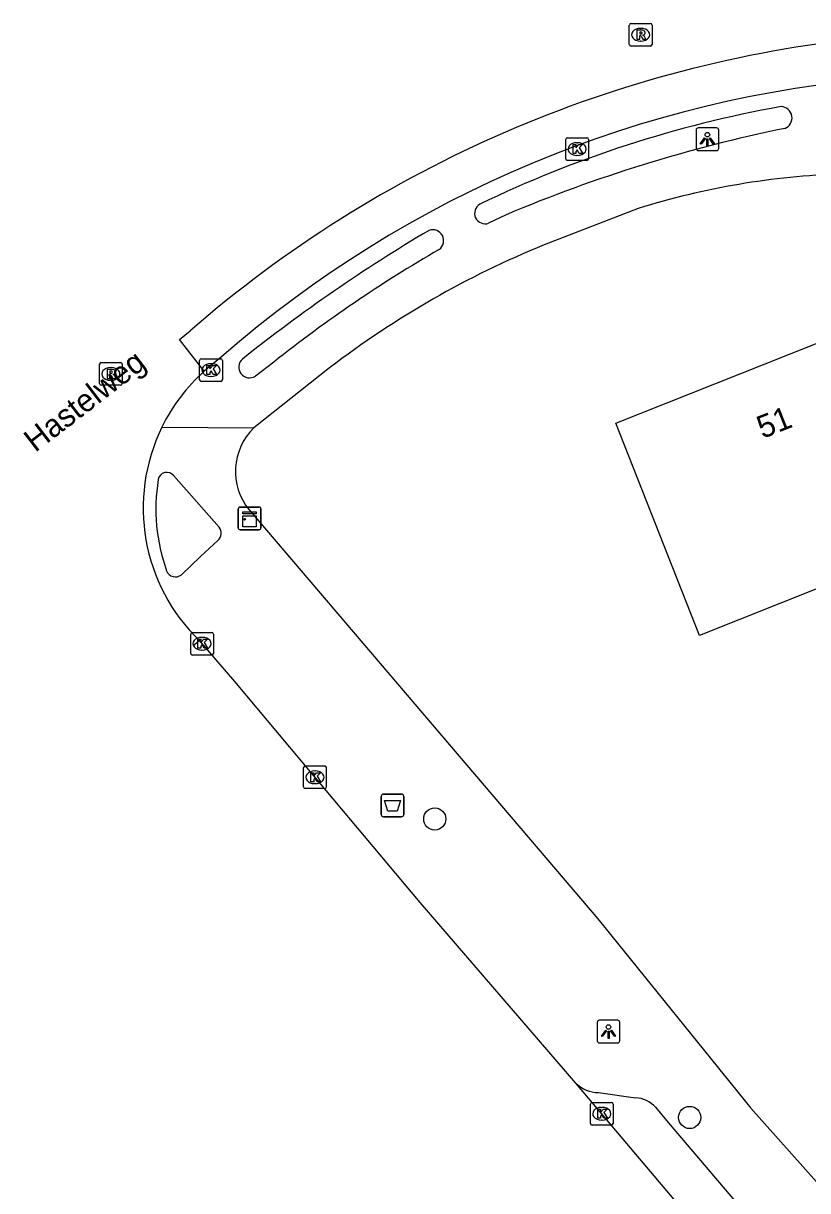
# Model space of a CAD drawing. Extents: x 159961 to 160856, y 382704 to 383353.
# Drawn here: x 159960.7 to 159995.3, y 383238.8 to 383290.2 of the extents above; entities that cross this region are included whole.
import ezdxf

# ---------------------------------------------------------------- set-up
doc = ezdxf.new("R2010")
doc.units = 0
for name, color, linetype in [('IMGEO_Afvalbak', 7, 'Continuous'), ('IMGEO_Boom', 7, 'Continuous'), ('IMGEO_Kast', 7, 'Continuous'), ('IMGEO_Kolk', 7, 'Continuous'), ('IMGEO_Lichtpunt', 7, 'Continuous'), ('IMGEO_Openbare_ruimte_label', 7, 'Continuous'), ('IMGEO_Pand', 7, 'Continuous'), ('IMGEO_Pand_nummerreeks', 7, 'Continuous'), ('IMGEO_Rijbaan_lokaal_gesloten', 7, 'Continuous'), ('IMGEO_Rijbaan_lokaal_open', 7, 'Continuous'), ('IMGEO_Rioolput', 7, 'Continuous'), ('IMGEO_Voetpad_open', 7, 'Continuous')]:
    doc.layers.add(name, color=color, linetype=linetype)

msp = doc.modelspace()

# ---------------------------------------------------------------- linework, layer by layer
at = {"layer": 'IMGEO_Afvalbak'}
for p, q in [((159976.475, 383255.351), (159976.475, 383256.151)), ((159976.475, 383256.151), (159976.475, 383255.351)), ((159976.575, 383256.251), (159977.365, 383256.251)), ((159977.365, 383256.251), (159976.575, 383256.251)), ((159977.465, 383256.151), (159977.465, 383255.351)), ((159977.465, 383255.351), (159977.465, 383256.151)), ((159977.365, 383255.251), (159976.575, 383255.251)), ((159976.575, 383255.251), (159977.365, 383255.251))]:
    msp.add_line(p, q, dxfattribs=at)
msp.add_lwpolyline([(159976.618, 383255.965), (159977.322, 383255.965), (159977.173, 383255.495), (159976.767, 383255.495), (159976.618, 383255.965)], dxfattribs=at)
for centre, start, end in [((159976.575, 383256.151), 90, 180), ((159976.575, 383256.151), 90, 180), ((159977.365, 383256.151), 0, 90), ((159977.365, 383256.151), 360, 90), ((159976.575, 383255.351), 180, 270), ((159976.575, 383255.351), 180, 270), ((159977.365, 383255.351), 270, 0), ((159977.365, 383255.351), 270, 0)]:
    msp.add_arc(centre, 0.1, start, end, dxfattribs=at)
at = {"layer": 'IMGEO_Boom'}
for centre in [(159978.834, 383255.154), (159990.063, 383242.015)]:
    msp.add_circle(centre, 0.489, dxfattribs=at)
at = {"layer": 'IMGEO_Kast'}
for p, q in [((159970.254, 383268.887), (159971.095, 383268.887)), ((159971.095, 383268.887), (159970.254, 383268.887)), ((159971.179, 383268.812), (159971.179, 383267.971)), ((159971.179, 383267.971), (159971.179, 383268.812)), ((159970.179, 383267.962), (159970.179, 383268.803)), ((159970.179, 383268.803), (159970.179, 383267.962)), ((159971.104, 383267.887), (159970.263, 383267.887)), ((159970.263, 383267.887), (159971.104, 383267.887))]:
    msp.add_line(p, q, dxfattribs=at)
for points in [[(159970.374, 383268.677), (159970.974, 383268.677), (159970.974, 383268.592), (159970.374, 383268.592), (159970.374, 383268.677)], [(159970.374, 383268.502), (159970.974, 383268.502), (159970.974, 383268.013), (159970.374, 383268.013), (159970.374, 383268.502)]]:
    msp.add_lwpolyline(points, dxfattribs=at)
msp.add_circle((159970.458, 383268.351), 0.0377, dxfattribs=at)
for centre, start, end in [((159970.257, 383268.809), 92.4484, 184.2845), ((159970.257, 383268.809), 92.4484, 184.2845), ((159971.101, 383268.809), 2.4484, 94.2845), ((159971.101, 383268.809), 2.4484, 94.2845), ((159970.257, 383267.965), 182.4484, 274.2845), ((159970.257, 383267.965), 182.4484, 274.2845), ((159971.101, 383267.965), 272.4484, 4.2845), ((159971.101, 383267.965), 272.4484, 4.2845)]:
    msp.add_arc(centre, 0.0779, start, end, dxfattribs=at)
at = {"layer": 'IMGEO_Kolk'}
for p, q in [((159984.603, 383284.217), (159984.603, 383285.069)), ((159984.678, 383285.143), (159985.53, 383285.143)), ((159985.091, 383284.923), (159985.116, 383284.923)), ((159985.604, 383285.069), (159985.604, 383284.217)), ((159985.114, 383284.363), (159985.089, 383284.363)), ((159985.53, 383284.143), (159984.678, 383284.143)), ((159968.478, 383274.491), (159968.478, 383275.343)), ((159968.553, 383275.417), (159969.405, 383275.417)), ((159968.966, 383275.197), (159968.991, 383275.197)), ((159969.479, 383275.343), (159969.479, 383274.491)), ((159968.989, 383274.637), (159968.964, 383274.637)), ((159969.405, 383274.417), (159968.553, 383274.417)), ((159968.084, 383262.444), (159968.084, 383263.296)), ((159968.159, 383263.37), (159969.011, 383263.37)), ((159969.085, 383263.296), (159969.085, 383262.444)), ((159968.572, 383263.15), (159968.597, 383263.15)), ((159969.011, 383262.37), (159968.159, 383262.37)), ((159968.595, 383262.59), (159968.57, 383262.59)), ((159973.056, 383256.565), (159973.056, 383257.417)), ((159973.131, 383257.491), (159973.983, 383257.491)), ((159973.544, 383257.271), (159973.569, 383257.271)), ((159974.057, 383257.417), (159974.057, 383256.565)), ((159973.983, 383256.491), (159973.131, 383256.491)), ((159973.567, 383256.711), (159973.542, 383256.711)), ((159985.689, 383241.751), (159985.689, 383242.603)), ((159985.764, 383242.677), (159986.616, 383242.677)), ((159986.69, 383242.603), (159986.69, 383241.751)), ((159986.177, 383242.457), (159986.202, 383242.457)), ((159986.616, 383241.677), (159985.764, 383241.677)), ((159986.2, 383241.897), (159986.175, 383241.897))]:
    msp.add_line(p, q, dxfattribs=at)
for points in [[(159984.603, 383284.217), (159984.603, 383285.069)], [(159984.678, 383285.143), (159985.53, 383285.143)], [(159984.924, 383284.843), (159985.047, 383284.843), (159985.047, 383284.692), (159985.177, 383284.843), (159985.341, 383284.843), (159985.195, 383284.692), (159985.348, 383284.443), (159985.196, 383284.443), (159985.111, 383284.607), (159985.047, 383284.54), (159985.047, 383284.443), (159984.924, 383284.443), (159984.924, 383284.843)], [(159985.604, 383285.069), (159985.604, 383284.217)], [(159985.53, 383284.143), (159984.678, 383284.143)], [(159968.478, 383274.491), (159968.478, 383275.343)], [(159968.553, 383275.417), (159969.405, 383275.417)], [(159968.799, 383275.117), (159968.922, 383275.117), (159968.922, 383274.966), (159969.052, 383275.117), (159969.216, 383275.117), (159969.07, 383274.966), (159969.223, 383274.717), (159969.071, 383274.717), (159968.986, 383274.881), (159968.922, 383274.814), (159968.922, 383274.717), (159968.799, 383274.717), (159968.799, 383275.117)], [(159969.479, 383275.343), (159969.479, 383274.491)], [(159969.405, 383274.417), (159968.553, 383274.417)], [(159968.084, 383262.444), (159968.084, 383263.296)], [(159968.159, 383263.37), (159969.011, 383263.37)], [(159969.085, 383263.296), (159969.085, 383262.444)], [(159968.405, 383263.07), (159968.528, 383263.07), (159968.528, 383262.919), (159968.658, 383263.07), (159968.822, 383263.07), (159968.676, 383262.919), (159968.829, 383262.67), (159968.677, 383262.67), (159968.592, 383262.834), (159968.528, 383262.767), (159968.528, 383262.67), (159968.405, 383262.67), (159968.405, 383263.07)], [(159969.011, 383262.37), (159968.159, 383262.37)], [(159973.056, 383256.565), (159973.056, 383257.417)], [(159973.131, 383257.491), (159973.983, 383257.491)], [(159973.377, 383257.191), (159973.5, 383257.191), (159973.5, 383257.04), (159973.63, 383257.191), (159973.794, 383257.191), (159973.648, 383257.04), (159973.801, 383256.791), (159973.649, 383256.791), (159973.564, 383256.955), (159973.5, 383256.888), (159973.5, 383256.791), (159973.377, 383256.791), (159973.377, 383257.191)], [(159974.057, 383257.417), (159974.057, 383256.565)], [(159973.983, 383256.491), (159973.131, 383256.491)], [(159985.689, 383241.751), (159985.689, 383242.603)], [(159985.764, 383242.677), (159986.616, 383242.677)], [(159986.69, 383242.603), (159986.69, 383241.751)], [(159986.01, 383242.377), (159986.133, 383242.377), (159986.133, 383242.226), (159986.263, 383242.377), (159986.427, 383242.377), (159986.281, 383242.226), (159986.434, 383241.977), (159986.282, 383241.977), (159986.197, 383242.141), (159986.133, 383242.074), (159986.133, 383241.977), (159986.01, 383241.977), (159986.01, 383242.377)], [(159986.616, 383241.677), (159985.764, 383241.677)]]:
    msp.add_lwpolyline(points, dxfattribs=at)
for centre, start, end in [((159984.68, 383285.067), 91.552, 178.448), ((159984.68, 383285.067), 91.552, 178.448), ((159985.528, 383285.067), 1.552, 88.448), ((159985.528, 383285.067), 1.552, 88.448), ((159984.68, 383284.219), 181.552, 268.448), ((159984.68, 383284.219), 181.552, 268.448), ((159985.528, 383284.219), 271.552, 358.448), ((159985.528, 383284.219), 271.552, 358.448), ((159968.555, 383275.341), 91.552, 178.448), ((159968.555, 383275.341), 91.552, 178.448), ((159969.403, 383275.341), 1.552, 88.448), ((159969.403, 383275.341), 1.552, 88.448), ((159968.555, 383274.493), 181.552, 268.448), ((159968.555, 383274.493), 181.552, 268.448), ((159969.403, 383274.493), 271.552, 358.448), ((159969.403, 383274.493), 271.552, 358.448), ((159968.161, 383263.294), 91.552, 178.448), ((159968.161, 383263.294), 91.552, 178.448), ((159969.009, 383263.294), 1.552, 88.448), ((159969.009, 383263.294), 1.552, 88.448), ((159968.161, 383262.446), 181.552, 268.448), ((159968.161, 383262.446), 181.552, 268.448), ((159969.009, 383262.446), 271.552, 358.448), ((159969.009, 383262.446), 271.552, 358.448), ((159973.133, 383257.415), 91.552, 178.448), ((159973.133, 383257.415), 91.552, 178.448), ((159973.981, 383257.415), 1.552, 88.448), ((159973.981, 383257.415), 1.552, 88.448), ((159973.133, 383256.567), 181.552, 268.448), ((159973.133, 383256.567), 181.552, 268.448), ((159973.981, 383256.567), 271.552, 358.448), ((159973.981, 383256.567), 271.552, 358.448), ((159985.766, 383242.601), 91.552, 178.448), ((159985.766, 383242.601), 91.552, 178.448), ((159986.614, 383242.601), 1.552, 88.448), ((159986.614, 383242.601), 1.552, 88.448), ((159985.766, 383241.753), 181.552, 268.448), ((159985.766, 383241.753), 181.552, 268.448), ((159986.614, 383241.753), 271.552, 358.448), ((159986.614, 383241.753), 271.552, 358.448)]:
    msp.add_arc(centre, 0.0765, start, end, dxfattribs=at)
for centre, major_axis, ratio, start_param, end_param in [((159985.09, 383284.643), (-0.387, 0.002), 0.722429, 4.712389, 7.853982), ((159985.115, 383284.643), (-0.39, 0.002), 0.717154, 1.570796, 4.712389), ((159968.965, 383274.917), (-0.387, 0.002), 0.722429, 4.712389, 7.853982), ((159968.99, 383274.917), (-0.39, 0.002), 0.717154, 1.570796, 4.712389), ((159968.571, 383262.87), (-0.387, 0.002), 0.722429, 4.712389, 7.853982), ((159968.596, 383262.87), (-0.39, 0.002), 0.717154, 1.570796, 4.712389), ((159973.543, 383256.991), (-0.387, 0.002), 0.722429, 4.712389, 7.853982), ((159973.568, 383256.991), (-0.39, 0.002), 0.717154, 1.570796, 4.712389), ((159986.176, 383242.177), (-0.387, 0.002), 0.722429, 4.712389, 7.853982), ((159986.201, 383242.177), (-0.39, 0.002), 0.717154, 1.570796, 4.712389)]:
    msp.add_ellipse(centre, major_axis=major_axis, ratio=ratio, start_param=start_param, end_param=end_param, dxfattribs=at)
at = {"layer": 'IMGEO_Lichtpunt'}
for p, q in [((159990.342, 383285.48), (159990.342, 383284.673)), ((159990.342, 383285.48), (159990.342, 383284.673)), ((159991.244, 383285.575), (159990.436, 383285.575)), ((159991.244, 383285.575), (159990.436, 383285.575)), ((159991.338, 383284.673), (159991.338, 383285.48)), ((159991.338, 383284.673), (159991.338, 383285.48)), ((159990.436, 383284.579), (159991.244, 383284.579)), ((159990.436, 383284.579), (159991.244, 383284.579)), ((159985.987, 383246.199), (159985.987, 383245.392)), ((159985.987, 383246.199), (159985.987, 383245.392)), ((159986.889, 383246.294), (159986.081, 383246.294)), ((159986.889, 383246.294), (159986.081, 383246.294)), ((159986.983, 383245.392), (159986.983, 383246.199)), ((159986.983, 383245.392), (159986.983, 383246.199)), ((159986.081, 383245.298), (159986.889, 383245.298)), ((159986.081, 383245.298), (159986.889, 383245.298))]:
    msp.add_line(p, q, dxfattribs=at)
for points in [[(159990.716, 383285.144), (159990.755, 383285.116), (159990.567, 383284.854), (159990.529, 383284.881), (159990.716, 383285.144)], [(159990.818, 383285.096), (159990.865, 383285.096), (159990.865, 383284.774), (159990.818, 383284.774), (159990.818, 383285.096)], [(159990.928, 383285.116), (159990.966, 383285.143), (159991.153, 383284.881), (159991.114, 383284.853), (159990.928, 383285.116)], [(159986.361, 383245.863), (159986.4, 383245.835), (159986.212, 383245.573), (159986.174, 383245.6), (159986.361, 383245.863)], [(159986.463, 383245.815), (159986.51, 383245.815), (159986.51, 383245.493), (159986.463, 383245.493), (159986.463, 383245.815)], [(159986.573, 383245.835), (159986.611, 383245.862), (159986.798, 383245.6), (159986.759, 383245.572), (159986.573, 383245.835)]]:
    msp.add_lwpolyline(points, dxfattribs=at)
for centre in [(159990.841, 383285.278), (159986.486, 383245.997)]:
    msp.add_circle(centre, 0.0994, dxfattribs=at)
for centre, start, end in [((159990.436, 383285.48), 90, 180), ((159990.436, 383285.48), 90, 180), ((159991.244, 383285.48), 0, 90), ((159991.244, 383285.48), 0, 90), ((159990.436, 383284.673), 180, 270), ((159990.436, 383284.673), 180, 270), ((159991.244, 383284.673), 270, 0), ((159991.244, 383284.673), 270, 360), ((159986.081, 383246.199), 90, 180), ((159986.081, 383246.199), 90, 180), ((159986.889, 383246.199), 0, 90), ((159986.889, 383246.199), 0, 90), ((159986.081, 383245.392), 180, 270), ((159986.081, 383245.392), 180, 270), ((159986.889, 383245.392), 270, 0), ((159986.889, 383245.392), 270, 360)]:
    msp.add_arc(centre, 0.0946, start, end, dxfattribs=at)
at = {"layer": 'IMGEO_Pand'}
msp.add_lwpolyline([(160002.018, 383262.712), (160000.276, 383267.111), (159998.559, 383266.431), (159999.041, 383265.213), (159996.252, 383264.107), (159995.769, 383265.324), (159990.498, 383263.234), (159986.81, 383272.583), (159998.885, 383277.371), (160002.407, 383268.436), (160010.962, 383271.828), (160013.55, 383265.303), (160005.184, 383261.986), (160002.018, 383262.712)], dxfattribs=at)
at = {"layer": 'IMGEO_Rijbaan_lokaal_gesloten'}
msp.add_lwpolyline([(159969.46, 383275.517), (159968.683, 383274.873)], dxfattribs=at)
msp.add_arc((160002.595, 383237.495), 50.435, 94.3795, 131.0712, dxfattribs=at)
at = {"layer": 'IMGEO_Rijbaan_lokaal_open'}
for points in [[(159968.683, 383274.873), (159967.594, 383276.266), (159968.06, 383276.648)], [(159968.468, 383263.009), (159968.231, 383262.808)], [(159985.049, 383243.527), (159978.189, 383251.472), (159972.977, 383257.683), (159970.034, 383261.211), (159968.468, 383263.009)], [(159995.149, 383231.573), (159985.049, 383243.527)]]:
    msp.add_lwpolyline(points, dxfattribs=at)
for centre, radius, start, end in [((160003.271, 383236.118), 53.689, 95.8341, 130.983), ((159974.098, 383268.836), 8.109, 131.8929, 153.9085), ((159974.09, 383268.841), 8.1, 153.9113, 226.0483)]:
    msp.add_arc(centre, radius, start, end, dxfattribs=at)
at = {"layer": 'IMGEO_Rioolput'}
for p, q in [((159987.402, 383289.253), (159987.402, 383290.105)), ((159987.477, 383290.179), (159988.329, 383290.179)), ((159987.89, 383289.959), (159987.915, 383289.959)), ((159988.403, 383290.105), (159988.403, 383289.253)), ((159987.913, 383289.399), (159987.888, 383289.399)), ((159988.329, 383289.179), (159987.477, 383289.179)), ((159964.068, 383274.319), (159964.068, 383275.171)), ((159964.143, 383275.245), (159964.995, 383275.245)), ((159964.556, 383275.025), (159964.581, 383275.025)), ((159965.069, 383275.171), (159965.069, 383274.319)), ((159964.579, 383274.465), (159964.554, 383274.465)), ((159964.995, 383274.245), (159964.143, 383274.245))]:
    msp.add_line(p, q, dxfattribs=at)
for points in [[(159987.402, 383289.253), (159987.402, 383290.105)], [(159987.477, 383290.179), (159988.329, 383290.179)], [(159987.991, 383289.877), (159987.739, 383289.879), (159987.739, 383289.479)], [(159988.403, 383290.105), (159988.403, 383289.253)], [(159987.739, 383289.479), (159987.863, 383289.479), (159987.863, 383289.641), (159987.874, 383289.641)], [(159987.917, 383289.798), (159987.863, 383289.798), (159987.863, 383289.717)], [(159987.863, 383289.717), (159987.915, 383289.717)], [(159987.921, 383289.612), (159987.992, 383289.479), (159988.132, 383289.479), (159988.067, 383289.605)], [(159988.329, 383289.179), (159987.477, 383289.179)], [(159964.068, 383274.319), (159964.068, 383275.171)], [(159964.143, 383275.245), (159964.995, 383275.245)], [(159965.069, 383275.171), (159965.069, 383274.319)], [(159964.657, 383274.943), (159964.405, 383274.945), (159964.405, 383274.545)], [(159964.405, 383274.545), (159964.529, 383274.545), (159964.529, 383274.707), (159964.54, 383274.707)], [(159964.583, 383274.864), (159964.529, 383274.864), (159964.529, 383274.783)], [(159964.529, 383274.783), (159964.581, 383274.783)], [(159964.587, 383274.678), (159964.658, 383274.545), (159964.798, 383274.545), (159964.733, 383274.671)], [(159964.995, 383274.245), (159964.143, 383274.245)]]:
    msp.add_lwpolyline(points, dxfattribs=at)
for centre, radius, start, end in [((159987.479, 383290.103), 0.0765, 91.552, 178.448), ((159987.479, 383290.103), 0.0765, 91.552, 178.448), ((159987.99, 383289.767), 0.109, 350.3612, 89.416), ((159988.327, 383290.103), 0.0765, 1.552, 88.448), ((159988.327, 383290.103), 0.0765, 1.552, 88.448), ((159987.873, 383289.588), 0.0533, 26.0293, 88.6989), ((159987.899, 383289.906), 0.19, 274.7715, 282.9687), ((159987.923, 383289.702), 0.0964, 77.0061, 93.1865), ((159987.937, 383289.759), 0.0378, 276.6634, 79.6772), ((159987.988, 383289.767), 0.112, 277.5842, 350.9817), ((159987.972, 383289.552), 0.108, 29.5134, 73.7905), ((159987.479, 383289.255), 0.0765, 181.552, 268.448), ((159987.479, 383289.255), 0.0765, 181.552, 268.448), ((159988.327, 383289.255), 0.0765, 271.552, 358.448), ((159988.327, 383289.255), 0.0765, 271.552, 358.448), ((159964.145, 383275.169), 0.0765, 91.552, 178.448), ((159964.145, 383275.169), 0.0765, 91.552, 178.448), ((159964.993, 383275.169), 0.0765, 1.552, 88.448), ((159964.993, 383275.169), 0.0765, 1.552, 88.448), ((159964.539, 383274.654), 0.0533, 26.0293, 88.6989), ((159964.565, 383274.972), 0.19, 274.7715, 282.9687), ((159964.589, 383274.768), 0.0964, 77.0061, 93.1865), ((159964.603, 383274.825), 0.0378, 276.6634, 79.6772), ((159964.656, 383274.833), 0.109, 350.3612, 89.416), ((159964.654, 383274.833), 0.112, 277.5842, 350.9817), ((159964.638, 383274.618), 0.108, 29.5134, 73.7905), ((159964.145, 383274.321), 0.0765, 181.552, 268.448), ((159964.145, 383274.321), 0.0765, 181.552, 268.448), ((159964.993, 383274.321), 0.0765, 271.552, 358.448), ((159964.993, 383274.321), 0.0765, 271.552, 358.448)]:
    msp.add_arc(centre, radius, start, end, dxfattribs=at)
for centre, major_axis, ratio, start_param, end_param in [((159987.889, 383289.679), (-0.387, 0.002), 0.722429, 4.712389, 7.853982), ((159987.914, 383289.679), (-0.39, 0.002), 0.717154, 1.570796, 4.712389), ((159964.555, 383274.745), (-0.387, 0.002), 0.722429, 4.712389, 7.853982), ((159964.58, 383274.745), (-0.39, 0.002), 0.717154, 1.570796, 4.712389)]:
    msp.add_ellipse(centre, major_axis=major_axis, ratio=ratio, start_param=start_param, end_param=end_param, dxfattribs=at)
at = {"layer": 'IMGEO_Voetpad_open'}
for points in [[(159981.972, 383281.755), (159981.205, 383281.382)], [(159987.792, 383282.028), (159983.656, 383280.429)], [(159974.199, 383275.009), (159970.863, 383272.367)], [(159971.74, 383275.266), (159970.931, 383274.652)], [(159966.815, 383272.403), (159970.863, 383272.367)], [(159967.334, 383270.256), (159969.34, 383267.997)], [(159970.658, 383268.765), (159986.013, 383250.759), (159992.759, 383242.419), (159998.051, 383236.487), (160000.542, 383236.934), (160005.149, 383238.457), (160013.087, 383206.7), (160019.094, 383183.073)], [(159969.28, 383267.417), (159968.518, 383266.716)], [(159968.518, 383266.716), (159967.676, 383265.902)], [(159986.043, 383243.114), (159987.677, 383242.878)], [(159988.551, 383242.461), (159989.116, 383241.789), (159994.546, 383235.403)]]:
    msp.add_lwpolyline(points, dxfattribs=at)
for centre, radius, start, end in [((160003.099, 383236.022), 51.289, 100.1221, 115.7556), ((159994.073, 383286.018), 0.495, 290.3812, 88.5628), ((160007.585, 383220.733), 66.179, 101.62919, 112.76972), ((159997.847, 383249.876), 33.688, 91.8526, 107.3662), ((159981.053, 383281.82), 0.464, 121.3471, 289.1147), ((160014.741, 383219.821), 71.122, 120.55448, 128.60501), ((159978.744, 383280.613), 0.48, 307.0757, 109.2397), ((160009.313, 383227.897), 60.461, 120.05341, 128.42181), ((159999.178, 383242.385), 41.089, 112.1957, 127.4401), ((159970.672, 383275.044), 0.47, 130.7167, 303.5118), ((159972.714, 383270.455), 2.661, 134.0699, 219.4154), ((159967.026, 383270.035), 0.379, 35.6158, 171.1086), ((159974.68, 383268.809), 8.13, 170.9031, 199.6247), ((159968.998, 383267.739), 0.428, 311.1667, 37.021), ((159967.416, 383266.239), 0.426, 202.271, 307.6046), ((159986.035, 383244.498), 1.384, 224.5548, 270.3202), ((159987.639, 383241.673), 1.205, 40.8081, 88.1787)]:
    msp.add_arc(centre, radius, start, end, dxfattribs=at)

# ---------------------------------------------------------------- texts
at = {"layer": 'IMGEO_Openbare_ruimte_label'}
msp.add_text('Hastelweg', height=1, rotation=37.6035, dxfattribs=at).set_placement((159961.236, 383271.268))
at = {"layer": 'IMGEO_Pand_nummerreeks'}
msp.add_text('51', height=1, rotation=21.6287, dxfattribs=at).set_placement((159993.269, 383271.882))

doc.saveas('drawing.dxf')
